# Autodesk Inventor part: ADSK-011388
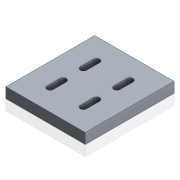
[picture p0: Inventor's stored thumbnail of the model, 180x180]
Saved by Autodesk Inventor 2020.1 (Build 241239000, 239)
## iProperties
Created: 2000-01
Part Number: ADSK-011388
Material: Pearson Aluminium
Document SubType Name: Modeling
Designer: sspink
Density: 2.71 g/cm^3
Appearance: Pearson-Aluminum
Mass: 163.871 g
Surface Area: 170.678 cm^2
Volume: 60.469 cm^3
Control State: 0
Checked Out: False
Master: False
Shininess: 35.0
Length Units: 11269
Angle Units: 11279
Time Units: 11290
Mass Units: 11283
Length Display Precision: 3
Angle Display Precision: 2
Compacted: True
Cutlength: 3.38
Material Desc: FLAT,ALUM,0.375X03.000
Material_number: A087231
Dimensions: 76x10x85 mm
Mass: 0,164 kg
DocNumber: ADSK-011388.ipt
Folder: 01 - Themengebiete\Simplification\01 - Packaging machine\
VDS_Category: 3D Komponenten
Density: 2.71
Volumn: 57.23583179242442
Area: 169.2551429436064
PropertySet Name: Model Information
Author: sspink
Revision Number: -
Title: base plate
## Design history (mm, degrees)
node "Rectangular Pattern1" dims "d12" = 20, "d14" = 32, "d15" = 20, "d17" = 32
node "Solide1"
  node "Extrusion1" dims "d2" = 85, "d3" = 0
  node "Extrusion2" dims "d10" = 101.6, "d11" = 0
sketch "Sketch1"
  geometry: L1 (38, 5)-(-38, 5); L2 (-38, 5)-(-38, -5); L3 (-38, -5)-(38, -5); L4 (38, -5)-(38, 5); 3 further points
  constraints: 8 end point, 2 midpoint, 2 perpendicular, 1 horizontal, 1 horizontal alignment, 1 parallel, 1 vertical alignment
  dimensions: "d0" = 10 distance of L1.end L2.end; "d1" = 76 distance of L1.end L1.start
sketch "Sketch2"
  geometry: L1 (-19, -32.75)-(-13, -32.75); L2 (-13, -32.75)-(-13, -20.25); L3 (-13, -20.25)-(-19, -20.25); L4 (-19, -20.25)-(-19, -32.75); L5 (-16, -32.75)-(-16, -20.25); L6 (-19, -26.5)-(-13, -26.5); L7 (-16, -26.5)-(16, -26.5); L8 (16, -26.5)-(16, -58.5); L9 (16, -58.5)-(-16, -58.5); L10 (-16, -58.5)-(-16, -26.5); L11 (-38, 0)-(-38, -85) reference; L12 (38, 0)-(-38, 0) reference; A1 r 3 centre (-16, -20.25) between (-13, -20.25) and (-19, -20.25); A2 r 3 centre (-16, -32.75) between (-19, -32.75) and (-13, -32.75); 6 further points
  constraints: 20 end point, 10 midpoint, 4 parallel, 4 point on circle, 2 centre point, 2 horizontal, 2 horizontal alignment, 2 perpendicular, 2 tangent, 2 vertical alignment
  dimensions: "d4" = 6 distance of L1.start L1.end; "d5" = 12.5 distance of L3.end L1.start; "d18" = 32 distance of L7.start L7.end; "d19" = 32 distance of L7.end L8.end (= d18)
node "Corps solides"
node "Corps surfaciques"
